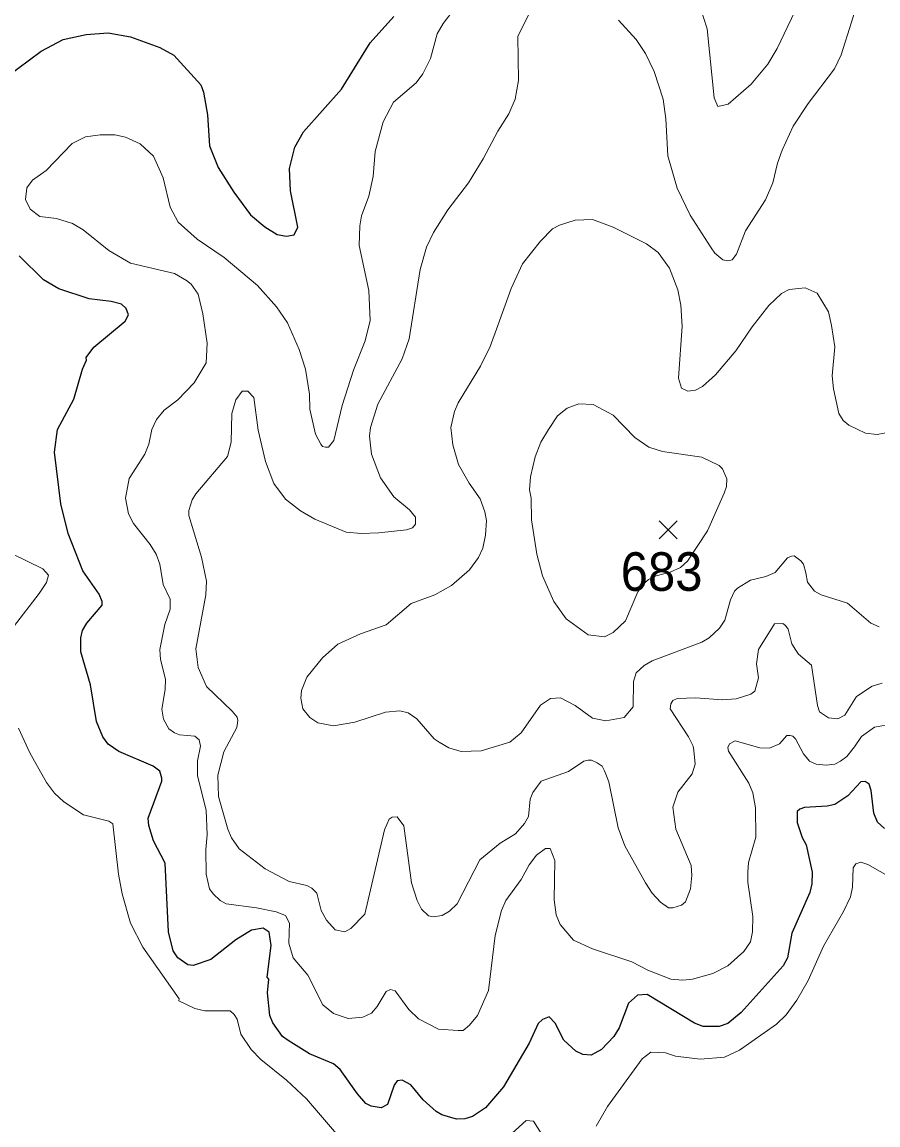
# Model space of a CAD drawing. Extents: x 294.2 to 320.3, y 7482.7 to 7510.7.
# Drawn here: x 298.568 to 300.344, y 7489.868 to 7492.157 of the extents above; entities that cross this region are included whole.
import ezdxf
from ezdxf.enums import TextEntityAlignment as Align

# ---------------------------------------------------------------- set-up
doc = ezdxf.new("R2010")
doc.units = 0
doc.header["$LTSCALE"] = 0.032
for name, color, linetype, lineweight in [('1', 7, 'Continuous', 25), ('2', 7, 'Continuous', 13), ('21', 7, 'Continuous', 25)]:
    doc.layers.add(name, color=color, linetype=linetype, lineweight=lineweight)
doc.layers.add('61', color=7, linetype='Continuous')

msp = doc.modelspace()

# ---------------------------------------------------------------- linework, layer by layer
at = {"layer": '1'}
for points in [[(298.4855, 7492.007), (298.6075, 7492.0971), (298.6534, 7492.1214), (298.7007, 7492.1316), (298.7467, 7492.1347), (298.7926, 7492.1265), (298.8539, 7492.1048), (298.8827, 7492.0888), (298.9388, 7492.0269), (298.9446, 7492.0116), (298.9529, 7491.9649), (298.9567, 7491.9005), (298.9746, 7491.8558), (299.0071, 7491.804), (299.0422, 7491.7574), (299.0716, 7491.7325), (299.0971, 7491.7166), (299.117, 7491.7127), (299.1329, 7491.7159), (299.14, 7491.7319), (299.1252, 7491.8072), (299.1227, 7491.8532), (299.1342, 7491.8979), (299.1521, 7491.9292), (299.2306, 7492.0179), (299.2906, 7492.1143), (299.3398, 7492.1692)], [(298.753, 7491.5774), (298.7071, 7491.5831), (298.6445, 7491.6035), (298.6126, 7491.6221), (298.5615, 7491.6719)], [(298.7007, 7491.4611), (298.7166, 7491.4822), (298.7817, 7491.5365), (298.7888, 7491.5493), (298.7837, 7491.5627), (298.7741, 7491.5716), (298.753, 7491.5774)], [(300.187, 7490.4645), (300.1954, 7490.4492), (300.2081, 7490.3924), (300.2075, 7490.3681), (300.203, 7490.3502), (300.166, 7490.266), (300.1564, 7490.2149), (300.1475, 7490.1982), (300.0606, 7490.1012), (300.0326, 7490.0782), (300.0147, 7490.0719), (299.9815, 7490.0719), (299.9636, 7490.0788), (299.8653, 7490.1383), (299.8454, 7490.137), (299.827, 7490.1204), (299.8071, 7490.0693), (299.7963, 7490.0514), (299.7708, 7490.0246), (299.7491, 7490.0125), (299.7318, 7490.0144), (299.7171, 7490.0208), (299.6922, 7490.0438), (299.6744, 7490.0788), (299.6622, 7490.0923), (299.6482, 7490.0865), (299.6392, 7490.0782), (299.6207, 7490.0374), (299.5671, 7489.9473), (299.53, 7489.9033), (299.5026, 7489.8854), (299.4866, 7489.8803), (299.4694, 7489.8796), (299.4394, 7489.8886), (299.4273, 7489.8956), (299.4004, 7489.9199), (299.3749, 7489.9512), (299.357, 7489.9608), (299.3462, 7489.9595), (299.3404, 7489.9505), (299.3264, 7489.9103), (299.3136, 7489.9033), (299.2925, 7489.9065), (299.2817, 7489.9122), (299.2638, 7489.9327), (299.2281, 7489.9831), (299.214, 7489.9946), (299.1642, 7490.0157), (299.1202, 7490.0431), (299.1086, 7490.0514), (299.0882, 7490.0795), (299.0825, 7490.0948), (299.0774, 7490.1421), (299.0799, 7490.1702), (299.0767, 7490.1748), (299.085, 7490.2404), (299.0806, 7490.2679), (299.0685, 7490.2762), (299.0438, 7490.2719), (299.0116, 7490.252), (298.9594, 7490.2112), (298.9229, 7490.1989), (298.912, 7490.2001), (298.8913, 7490.2145), (298.8813, 7490.229), (298.8718, 7490.2685), (298.8648, 7490.4115), (298.8405, 7490.4575), (298.8309, 7490.4894), (298.8297, 7490.5047), (298.8578, 7490.5814), (298.8578, 7490.5877), (298.8539, 7490.6024), (298.8399, 7490.6126), (298.769, 7490.6433), (298.7466, 7490.6586), (298.7352, 7490.6733), (298.7224, 7490.7052), (298.7102, 7490.7818), (298.6898, 7490.8501), (298.6898, 7490.8789), (298.6936, 7490.8942), (298.7026, 7490.9095), (298.7339, 7490.9472), (298.7339, 7490.9542), (298.7281, 7490.9696), (298.6943, 7491.0181), (298.6637, 7491.096), (298.6483, 7491.1573), (298.6349, 7491.2645), (298.6413, 7491.3118), (298.6751, 7491.3744), (298.693, 7491.4369), (298.7013, 7491.4554), (298.7007, 7491.4611)], [(300.3582, 7490.483), (300.3435, 7490.4964), (300.3358, 7490.515), (300.3301, 7490.5622), (300.3262, 7490.5756), (300.3179, 7490.5807), (300.309, 7490.5801), (300.2822, 7490.5513), (300.2547, 7490.5334)], [(300.2547, 7490.5334), (300.2394, 7490.5296), (300.1922, 7490.527), (300.182, 7490.5233), (300.1768, 7490.5187), (300.1768, 7490.4958), (300.187, 7490.4645)]]:
    msp.add_lwpolyline(points, dxfattribs=at)
at = {"layer": '2'}
for points in [[(300.3103, 7492.2248), (300.2899, 7492.1571), (300.2681, 7492.0894), (300.2541, 7492.0601), (300.1998, 7491.9886), (300.1685, 7491.9413), (300.1456, 7491.8915), (300.1359, 7491.8647), (300.1264, 7491.8238), (300.1111, 7491.7881), (300.0696, 7491.7242), (300.0511, 7491.6757), (300.0421, 7491.6636), (300.0326, 7491.6616), (300.0223, 7491.6636), (300.0057, 7491.6776), (299.998, 7491.6885), (299.9546, 7491.7562), (299.9278, 7491.8123), (299.9086, 7491.88), (299.9042, 7491.9566), (299.8984, 7491.9975), (299.88, 7492.055), (299.8621, 7492.092), (299.8423, 7492.1214), (299.8059, 7492.1616)], [(300.1794, 7492.1954), (300.1353, 7492.1022), (300.1162, 7492.0703), (300.0811, 7492.0288), (300.0338, 7491.9866), (300.0121, 7491.9821), (300.0044, 7492.0001), (299.9898, 7492.1431), (299.9668, 7492.2146)], [(299.4675, 7492.1878), (299.442, 7492.1546), (299.4298, 7492.1329), (299.4157, 7492.0818), (299.3998, 7492.0499), (299.3858, 7492.0313), (299.3391, 7491.9911), (299.3174, 7491.9503), (299.3008, 7491.889), (299.297, 7491.8366), (299.288, 7491.7957), (299.2727, 7491.7549), (299.2689, 7491.7345), (299.2676, 7491.6936), (299.288, 7491.6004), (299.2906, 7491.5378), (299.2804, 7491.4957), (299.2561, 7491.4344), (299.2325, 7491.3616), (299.2153, 7491.2888), (299.2038, 7491.2747), (299.1974, 7491.2747), (299.1917, 7491.276), (299.1878, 7491.2811), (299.177, 7491.3016), (299.1655, 7491.3539), (299.1642, 7491.3846), (299.1559, 7491.4369), (299.1432, 7491.4778), (299.1189, 7491.5333), (299.0959, 7491.5659), (299.0563, 7491.6106), (298.9874, 7491.6687), (298.9311, 7491.707), (298.8916, 7491.7421), (298.8756, 7491.7728), (298.8609, 7491.8341), (298.8405, 7491.8787), (298.8131, 7491.9043), (298.7824, 7491.9183), (298.7607, 7491.9234), (298.7301, 7491.9234), (298.6994, 7491.9189), (298.6719, 7491.9055), (298.6177, 7491.8493), (298.5896, 7491.8295), (298.5781, 7491.8136), (298.5749, 7491.7893), (298.5844, 7491.7689), (298.6049, 7491.7536), (298.6394, 7491.7497), (298.6726, 7491.7395), (298.6949, 7491.7261), (298.7479, 7491.6833), (298.7926, 7491.6572), (298.8846, 7491.6355), (298.9095, 7491.6208), (298.919, 7491.6131), (298.9337, 7491.5927), (298.9433, 7491.5518), (298.9522, 7491.4906), (298.9497, 7491.4497), (298.9248, 7491.4082), (298.891, 7491.373), (298.8628, 7491.352), (298.8469, 7491.3322), (298.8373, 7491.3118), (298.8309, 7491.2811), (298.8226, 7491.2607), (298.79, 7491.2096), (298.7824, 7491.1688), (298.7888, 7491.1368), (298.799, 7491.1164), (298.8341, 7491.073), (298.8462, 7491.0526), (298.8539, 7491.0321), (298.8609, 7490.99), (298.8756, 7490.9593), (298.8756, 7490.9389), (298.8641, 7490.907), (298.8539, 7490.8546), (298.8552, 7490.8342), (298.8654, 7490.7933), (298.8648, 7490.7716), (298.8577, 7490.7308), (298.8615, 7490.7103), (298.8724, 7490.6905), (298.8846, 7490.6822), (298.8948, 7490.6778), (298.9267, 7490.6752), (298.9356, 7490.6675), (298.9382, 7490.6542), (298.9318, 7490.6235), (298.9318, 7490.5929), (298.9503, 7490.5213)], [(299.6194, 7492.1724), (299.5971, 7492.1277), (299.5983, 7492.0358), (299.5914, 7491.9975), (299.5786, 7491.9669), (299.5556, 7491.9311), (299.525, 7491.8736), (299.4943, 7491.8238), (299.4515, 7491.7677), (299.4221, 7491.7204), (299.4075, 7491.6898), (299.394, 7491.6438), (299.3717, 7491.4995), (299.357, 7491.4586), (299.3066, 7491.3641), (299.2913, 7491.3156), (299.2893, 7491.2977), (299.2932, 7491.2607), (299.3117, 7491.2109), (299.3398, 7491.1719), (299.3723, 7491.1445), (299.3845, 7491.1298), (299.3845, 7491.1151), (299.3781, 7491.1074), (299.366, 7491.1036), (299.3085, 7491.0972), (299.2715, 7491.0959), (299.2408, 7491.0985)], [(299.4796, 7490.6433), (299.4534, 7490.651), (299.4336, 7490.6624), (299.4234, 7490.6694), (299.387, 7490.711), (299.3692, 7490.7231), (299.3519, 7490.7276), (299.3225, 7490.725), (299.2587, 7490.7039), (299.214, 7490.6962), (299.1821, 7490.7026), (299.1655, 7490.7135), (299.1508, 7490.7314), (299.1463, 7490.7538), (299.1476, 7490.7697), (299.1591, 7490.7972), (299.1917, 7490.8374), (299.223, 7490.8661), (299.2702, 7490.8872), (299.3238, 7490.9063), (299.3755, 7490.9504), (299.4247, 7490.9682), (299.4592, 7490.9874), (299.4968, 7491.02), (299.5153, 7491.0455), (299.5243, 7491.0653), (299.5301, 7491.0921), (299.5319, 7491.1228), (299.5288, 7491.1407), (299.5186, 7491.1675), (299.4956, 7491.2), (299.4739, 7491.239), (299.4617, 7491.2799), (299.4579, 7491.3156), (299.4655, 7491.3488), (299.4732, 7491.3667), (299.5198, 7491.4433), (299.5396, 7491.4842), (299.5556, 7491.5276), (299.583, 7491.6042), (299.6067, 7491.6553), (299.6437, 7491.7025), (299.6686, 7491.728), (299.6833, 7491.7357), (299.7159, 7491.7459), (299.7516, 7491.7472), (299.795, 7491.7313), (299.864, 7491.6968), (299.8883, 7491.6789), (299.9119, 7491.6463), (299.9291, 7491.6017), (299.9355, 7491.5697), (299.938, 7491.5263), (299.9304, 7491.4178), (299.9368, 7491.3973), (299.9496, 7491.3909), (299.9655, 7491.3929), (299.9802, 7491.4011), (300.007, 7491.4248), (300.0498, 7491.4746), (300.0836, 7491.525), (300.1181, 7491.569), (300.1443, 7491.5939), (300.1602, 7491.6023), (300.1935, 7491.6054), (300.2183, 7491.5946), (300.2419, 7491.5557), (300.2483, 7491.5276)], [(300.2483, 7491.5276), (300.2547, 7491.4829), (300.2496, 7491.4229), (300.2521, 7491.3961), (300.263, 7491.345), (300.272, 7491.3303), (300.2841, 7491.3207), (300.3186, 7491.3041), (300.3429, 7491.3015), (300.3863, 7491.3092)], [(299.0582, 7491.3105), (299.0487, 7491.3782), (299.0365, 7491.3909), (299.0244, 7491.3909), (299.0116, 7491.3731), (299.0033, 7491.345), (299.002, 7491.285), (298.9943, 7491.2556), (298.9286, 7491.1783), (298.921, 7491.1655), (298.9139, 7491.1432), (298.9139, 7491.133), (298.9401, 7491.0462), (298.9509, 7490.9964), (298.9491, 7490.9683), (298.9286, 7490.8559), (298.9331, 7490.8176), (298.9509, 7490.778), (299.004, 7490.7269), (299.0142, 7490.7142), (299.0155, 7490.7078), (299.0135, 7490.6931), (298.9867, 7490.6427), (298.9739, 7490.5941), (298.9759, 7490.5494), (298.995, 7490.4818), (299.0027, 7490.4639), (299.0186, 7490.4409), (299.0723, 7490.3994), (299.1221, 7490.3732), (299.1591, 7490.3649), (299.1693, 7490.3591), (299.1795, 7490.3489), (299.1884, 7490.3132), (299.2, 7490.2928), (299.2178, 7490.2729), (299.2376, 7490.2685), (299.2504, 7490.2755), (299.2791, 7490.3055), (299.32, 7490.4805), (299.3302, 7490.5028), (299.336, 7490.5066), (299.3468, 7490.5073), (299.3602, 7490.4887), (299.3762, 7490.3707), (299.3883, 7490.3336), (299.3973, 7490.3158), (299.4113, 7490.3017), (299.4209, 7490.2998), (299.44, 7490.3029), (299.4554, 7490.3113), (299.4713, 7490.3266), (299.5179, 7490.4179), (299.5601, 7490.453), (299.592, 7490.4722), (299.6111, 7490.4939), (299.6188, 7490.5079), (299.6226, 7490.5443), (299.6284, 7490.5577), (299.6456, 7490.5813), (299.7018, 7490.6017), (299.7343, 7490.6229), (299.7427, 7490.6254), (299.7497, 7490.6254), (299.7618, 7490.6196), (299.772, 7490.6126), (299.7771, 7490.603), (299.7861, 7490.5801), (299.8052, 7490.4843), (299.8193, 7490.4473), (299.8621, 7490.3707), (299.8761, 7490.349), (299.8933, 7490.3304), (299.9099, 7490.3189), (299.9189, 7490.3189), (299.9368, 7490.3241), (299.945, 7490.3311), (299.9553, 7490.3579), (299.9584, 7490.386), (299.9566, 7490.4064), (299.9252, 7490.4818), (299.9189, 7490.5277), (299.9291, 7490.5584), (299.9591, 7490.5967), (299.9648, 7490.6171), (299.9623, 7490.6452), (299.961, 7490.6542), (299.9515, 7490.6733), (299.9132, 7490.732), (299.9144, 7490.7423), (299.9189, 7490.7492), (299.9278, 7490.7531), (299.9662, 7490.7544), (300.0211, 7490.7506), (300.0504, 7490.7524)], [(299.2408, 7491.0985), (299.1757, 7491.1253), (299.1457, 7491.1426), (299.115, 7491.1668), (299.0908, 7491.1994), (299.0735, 7491.2454), (299.0582, 7491.3105)], [(298.55, 7490.9019), (298.6036, 7490.9708), (298.6183, 7490.9938), (298.6228, 7491.0091), (298.6107, 7491.0225), (298.5155, 7491.0685)], [(300.3467, 7490.9018), (300.3294, 7490.9095), (300.2815, 7490.951), (300.2267, 7490.9682), (300.2126, 7490.9759), (300.1985, 7490.9944), (300.1947, 7491.0143), (300.1896, 7491.0321), (300.1845, 7491.0391), (300.1704, 7491.0494), (300.1647, 7491.0487), (300.157, 7491.0449), (300.1308, 7491.0149), (300.1117, 7491.0065), (300.0798, 7490.9989), (300.053, 7490.9823), (300.0466, 7490.9759), (300.0383, 7490.9581), (300.0268, 7490.9159), (300.0153, 7490.8993), (299.9942, 7490.8789), (299.9789, 7490.8699), (299.8755, 7490.831), (299.8595, 7490.8214), (299.8429, 7490.8061), (299.8371, 7490.7882), (299.8365, 7490.7359), (299.8174, 7490.7135), (299.7797, 7490.7065), (299.7516, 7490.7122), (299.7158, 7490.7384), (299.6852, 7490.7544)], [(300.0504, 7490.7524), (300.0804, 7490.762), (300.0887, 7490.7684), (300.0964, 7490.7959), (300.0925, 7490.8253), (300.0964, 7490.8546), (300.1296, 7490.9082)], [(300.1296, 7490.9082), (300.1468, 7490.9089), (300.1526, 7490.9044), (300.1583, 7490.8968), (300.166, 7490.8667), (300.1737, 7490.8534), (300.1794, 7490.845), (300.2062, 7490.8221), (300.2189, 7490.7384), (300.2234, 7490.7256), (300.242, 7490.7129), (300.2611, 7490.711), (300.2758, 7490.7186), (300.3, 7490.7575), (300.3326, 7490.7786), (300.3531, 7490.785)], [(299.6852, 7490.7544), (299.6648, 7490.7531), (299.6443, 7490.7391), (299.6041, 7490.6816), (299.5805, 7490.6624), (299.5205, 7490.6446), (299.4796, 7490.6433)], [(298.979, 7490.3336), (298.9918, 7490.3266), (299.0544, 7490.3183), (299.0953, 7490.31), (299.1144, 7490.3023), (299.1233, 7490.2864), (299.1214, 7490.2455), (299.1304, 7490.2149), (299.161, 7490.1791), (299.1923, 7490.1172), (299.214, 7490.0993), (299.2447, 7490.0891), (299.2753, 7490.0916), (299.2932, 7490.0999), (299.3053, 7490.114), (299.3238, 7490.1446), (299.3327, 7490.1491), (299.3423, 7490.1465), (299.371, 7490.1076), (299.3909, 7490.0878), (299.4324, 7490.0667), (299.4733, 7490.0636), (299.4834, 7490.0642), (299.4969, 7490.075), (299.5135, 7490.0948), (299.5358, 7490.1472), (299.5498, 7490.2608), (299.5633, 7490.3132), (299.5722, 7490.3336), (299.6041, 7490.3771), (299.6207, 7490.4077), (299.636, 7490.4281), (299.6546, 7490.4415), (299.6641, 7490.4415), (299.6737, 7490.4166), (299.6724, 7490.3349), (299.6762, 7490.3043), (299.6846, 7490.2838), (299.7127, 7490.2513), (299.7516, 7490.2334), (299.8334, 7490.2066), (299.8666, 7490.1893), (299.9144, 7490.1702), (299.9393, 7490.1683), (299.9598, 7490.1708), (300.0019, 7490.1823), (300.0326, 7490.1982), (300.0664, 7490.2276), (300.0798, 7490.2481), (300.0843, 7490.2685), (300.0849, 7490.3004), (300.0746, 7490.3719), (300.0746, 7490.3924), (300.0759, 7490.4128), (300.0912, 7490.4652), (300.09, 7490.5265), (300.0849, 7490.5571), (300.0766, 7490.5775), (300.0345, 7490.6439), (300.0332, 7490.6516), (300.0364, 7490.6592), (300.0479, 7490.665), (300.099, 7490.651), (300.1194, 7490.6503), (300.1404, 7490.6593), (300.1551, 7490.6765), (300.1621, 7490.6765), (300.1679, 7490.6752), (300.173, 7490.6695), (300.1902, 7490.6382), (300.2024, 7490.6228), (300.2164, 7490.6171), (300.2369, 7490.6145), (300.2553, 7490.6171), (300.2668, 7490.6229), (300.2796, 7490.6324), (300.2956, 7490.6529), (300.3103, 7490.6745), (300.3371, 7490.6937), (300.3677, 7490.6995)], [(299.2453, 7489.8203), (299.1585, 7489.9218), (299.1169, 7489.9607), (299.0633, 7490.0035), (299.0435, 7490.0246), (299.0218, 7490.0565), (299.0142, 7490.0872), (299.0084, 7490.0974), (298.9995, 7490.1044), (298.9471, 7490.1044), (298.9267, 7490.1095), (298.8935, 7490.1255), (298.8941, 7490.1299), (298.8188, 7490.2366), (298.7926, 7490.2864), (298.7754, 7490.3477), (298.7677, 7490.3885), (298.7562, 7490.4926), (298.7479, 7490.4983), (298.6956, 7490.5118), (298.6547, 7490.5386), (298.6349, 7490.5565), (298.6183, 7490.5788), (298.5838, 7490.6401), (298.5602, 7490.6912)], [(298.9503, 7490.5213), (298.9522, 7490.4703), (298.949, 7490.4396), (298.9497, 7490.3885), (298.9567, 7490.3579), (298.9643, 7490.3477), (298.979, 7490.3336)], [(300.3748, 7490.3796), (300.3237, 7490.4083), (300.309, 7490.4134), (300.2988, 7490.4096), (300.293, 7490.4013), (300.2917, 7490.3617), (300.2873, 7490.3413), (300.2733, 7490.3107), (300.2311, 7490.2391), (300.1998, 7490.1676)], [(300.1998, 7490.1676), (300.1762, 7490.1268), (300.1538, 7490.0967), (300.1341, 7490.0769), (300.0568, 7490.0233), (300.0262, 7490.0086), (299.9751, 7490.0041)], [(299.9751, 7490.0041), (299.924, 7490.0105), (299.9036, 7490.0176), (299.8729, 7490.0189), (299.855, 7490.0054), (299.7829, 7489.9059), (299.7593, 7489.865)], [(299.6507, 7489.842), (299.6297, 7489.8758), (299.6143, 7489.8771), (299.5556, 7489.8241)]]:
    msp.add_lwpolyline(points, dxfattribs=at)
msp.add_lwpolyline([(300.0254, 7491.1795), (299.991, 7491.1011), (299.9492, 7491.0383), (299.9343, 7491.0253), (299.9132, 7491.0151), (299.8838, 7491.0076), (299.868, 7491.0001), (299.8547, 7490.9882), (299.8458, 7490.9748), (299.8205, 7490.9146), (299.795, 7490.8904), (299.7772, 7490.8814), (299.7427, 7490.8852), (299.6973, 7490.9184), (299.6718, 7490.9542), (299.6481, 7491.0079), (299.6367, 7491.0526), (299.6252, 7491.1241), (299.6246, 7491.1688), (299.6213, 7491.1866), (299.6233, 7491.2135), (299.6328, 7491.2549), (299.645, 7491.285), (299.6603, 7491.3118), (299.6795, 7491.3399), (299.6992, 7491.3558), (299.7235, 7491.3648), (299.7535, 7491.3635), (299.795, 7491.3411), (299.8397, 7491.2951), (299.8691, 7491.2747), (299.8972, 7491.2658), (299.9789, 7491.2543), (300.0147, 7491.2371), (300.0217, 7491.23), (300.0306, 7491.2089), (300.03, 7491.193)], close=True, dxfattribs=at)
at = {"layer": '21'}
for p, q in [((299.89, 7491.122), (299.9275, 7491.0845)), ((299.9275, 7491.122), (299.89, 7491.0845))]:
    msp.add_line(p, q, dxfattribs=at)

# ---------------------------------------------------------------- texts
at = {"layer": '61', "width": 0.95}
msp.add_text('683', height=0.08, dxfattribs=at).set_placement((299.8954, 7490.9767), align=Align.CENTER)

doc.saveas('drawing.dxf')
